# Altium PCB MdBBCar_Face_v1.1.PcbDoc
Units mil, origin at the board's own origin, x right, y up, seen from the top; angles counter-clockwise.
Board outline 2202.88 x 1898.45 mil, 4 copper layers (Top Layer, GND, SIG, Bottom Layer), stack 23.756 mil thick; 72 components, 66 nets, 300 pads, 287 vias.
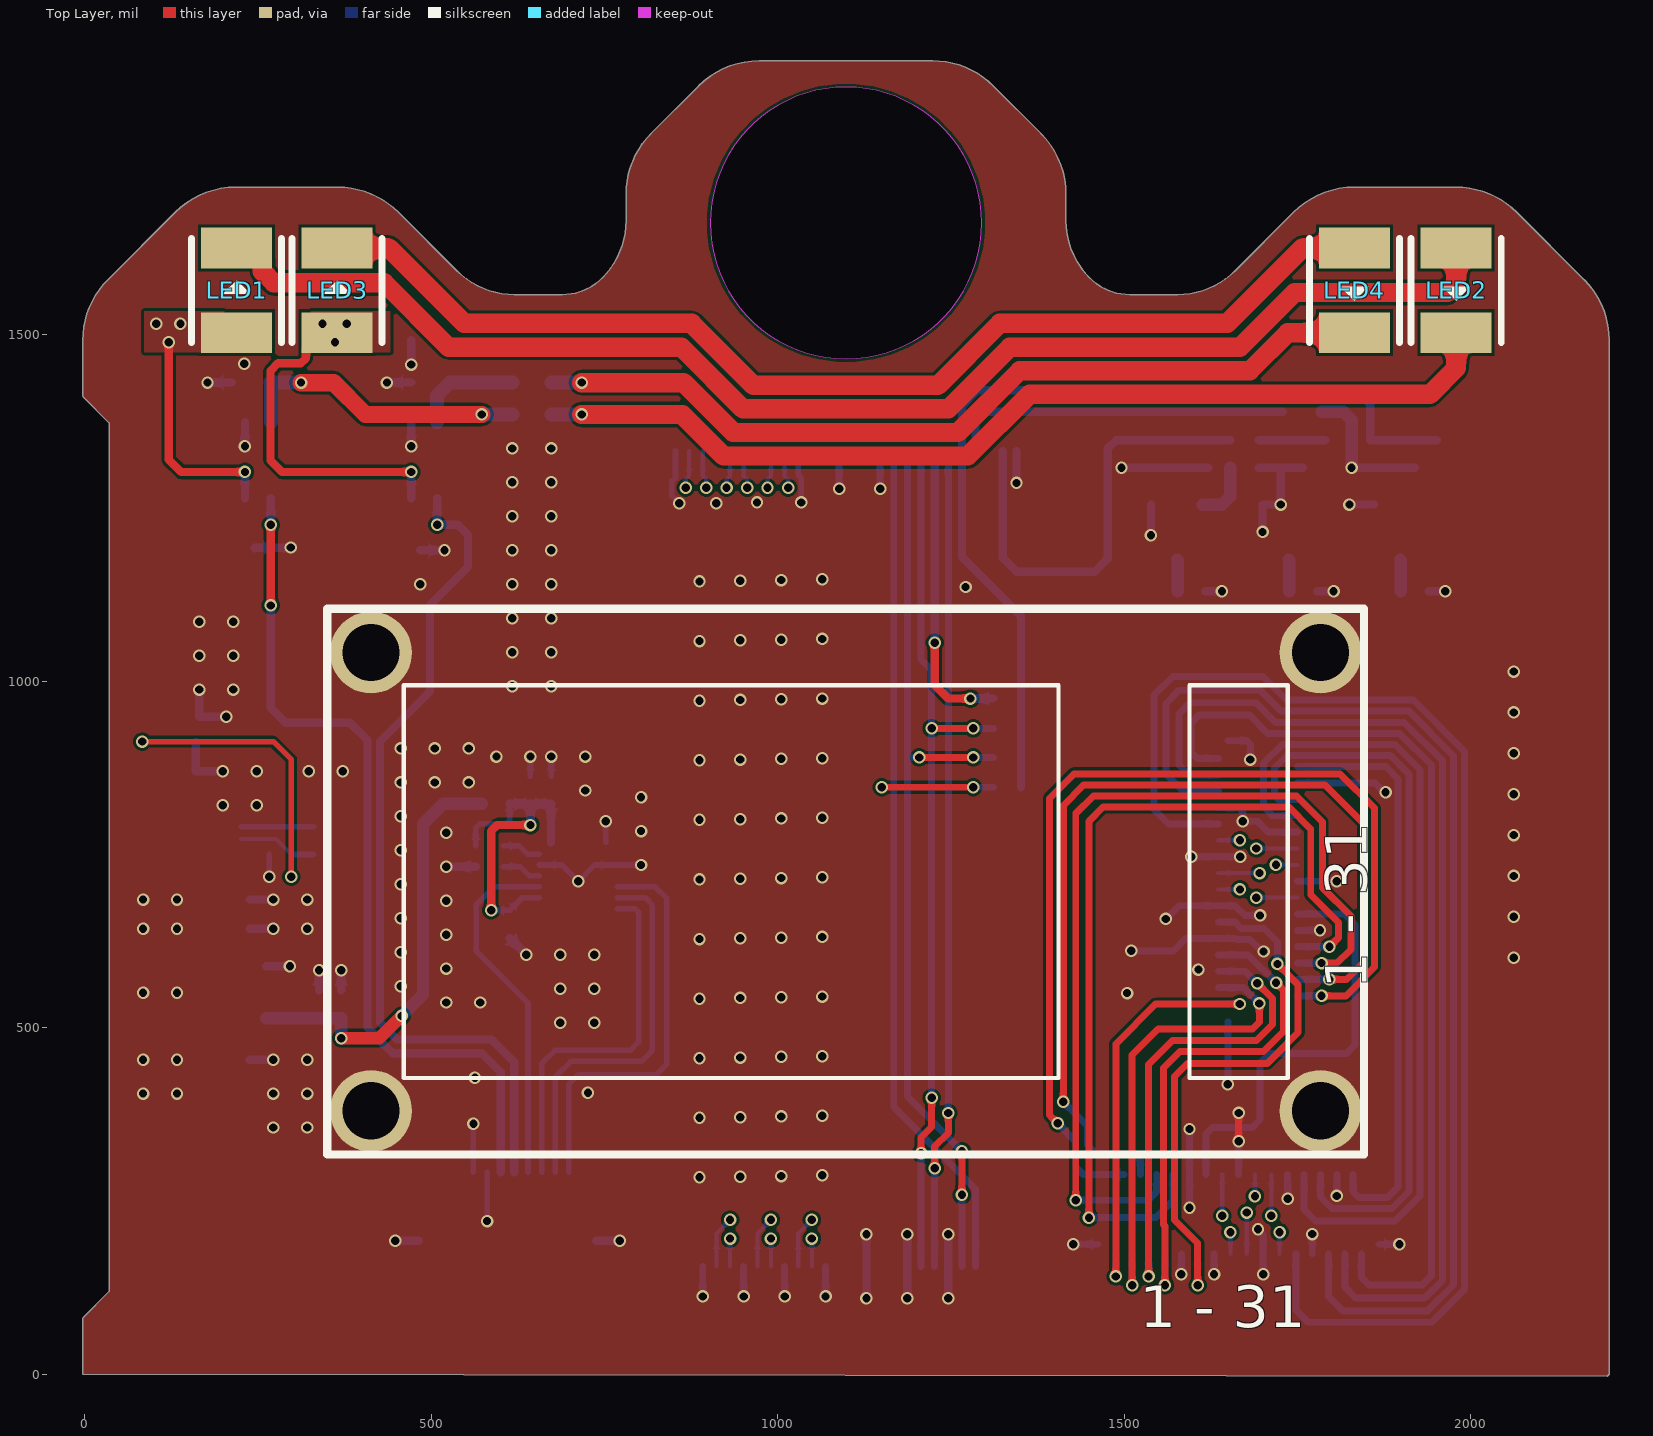
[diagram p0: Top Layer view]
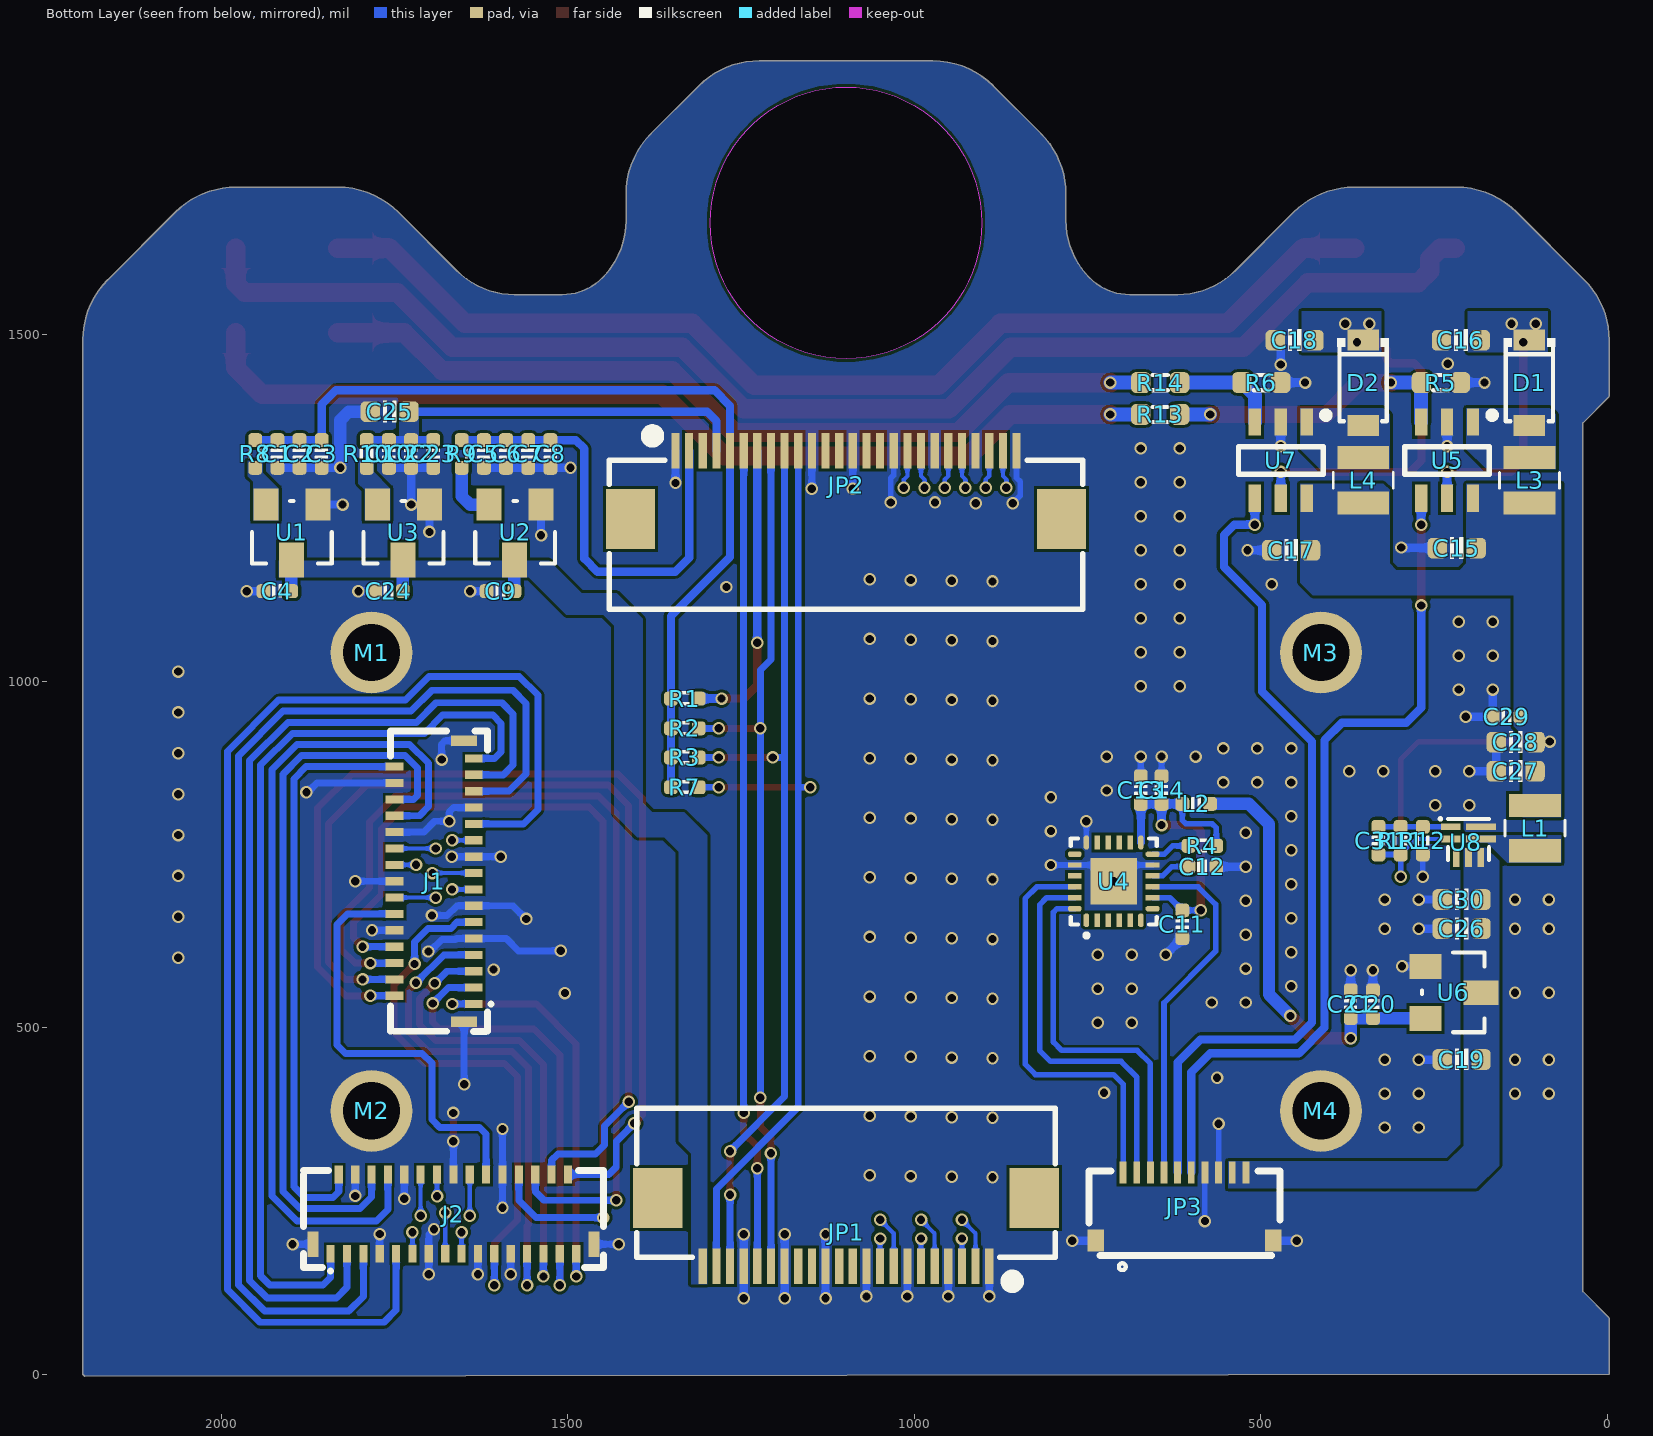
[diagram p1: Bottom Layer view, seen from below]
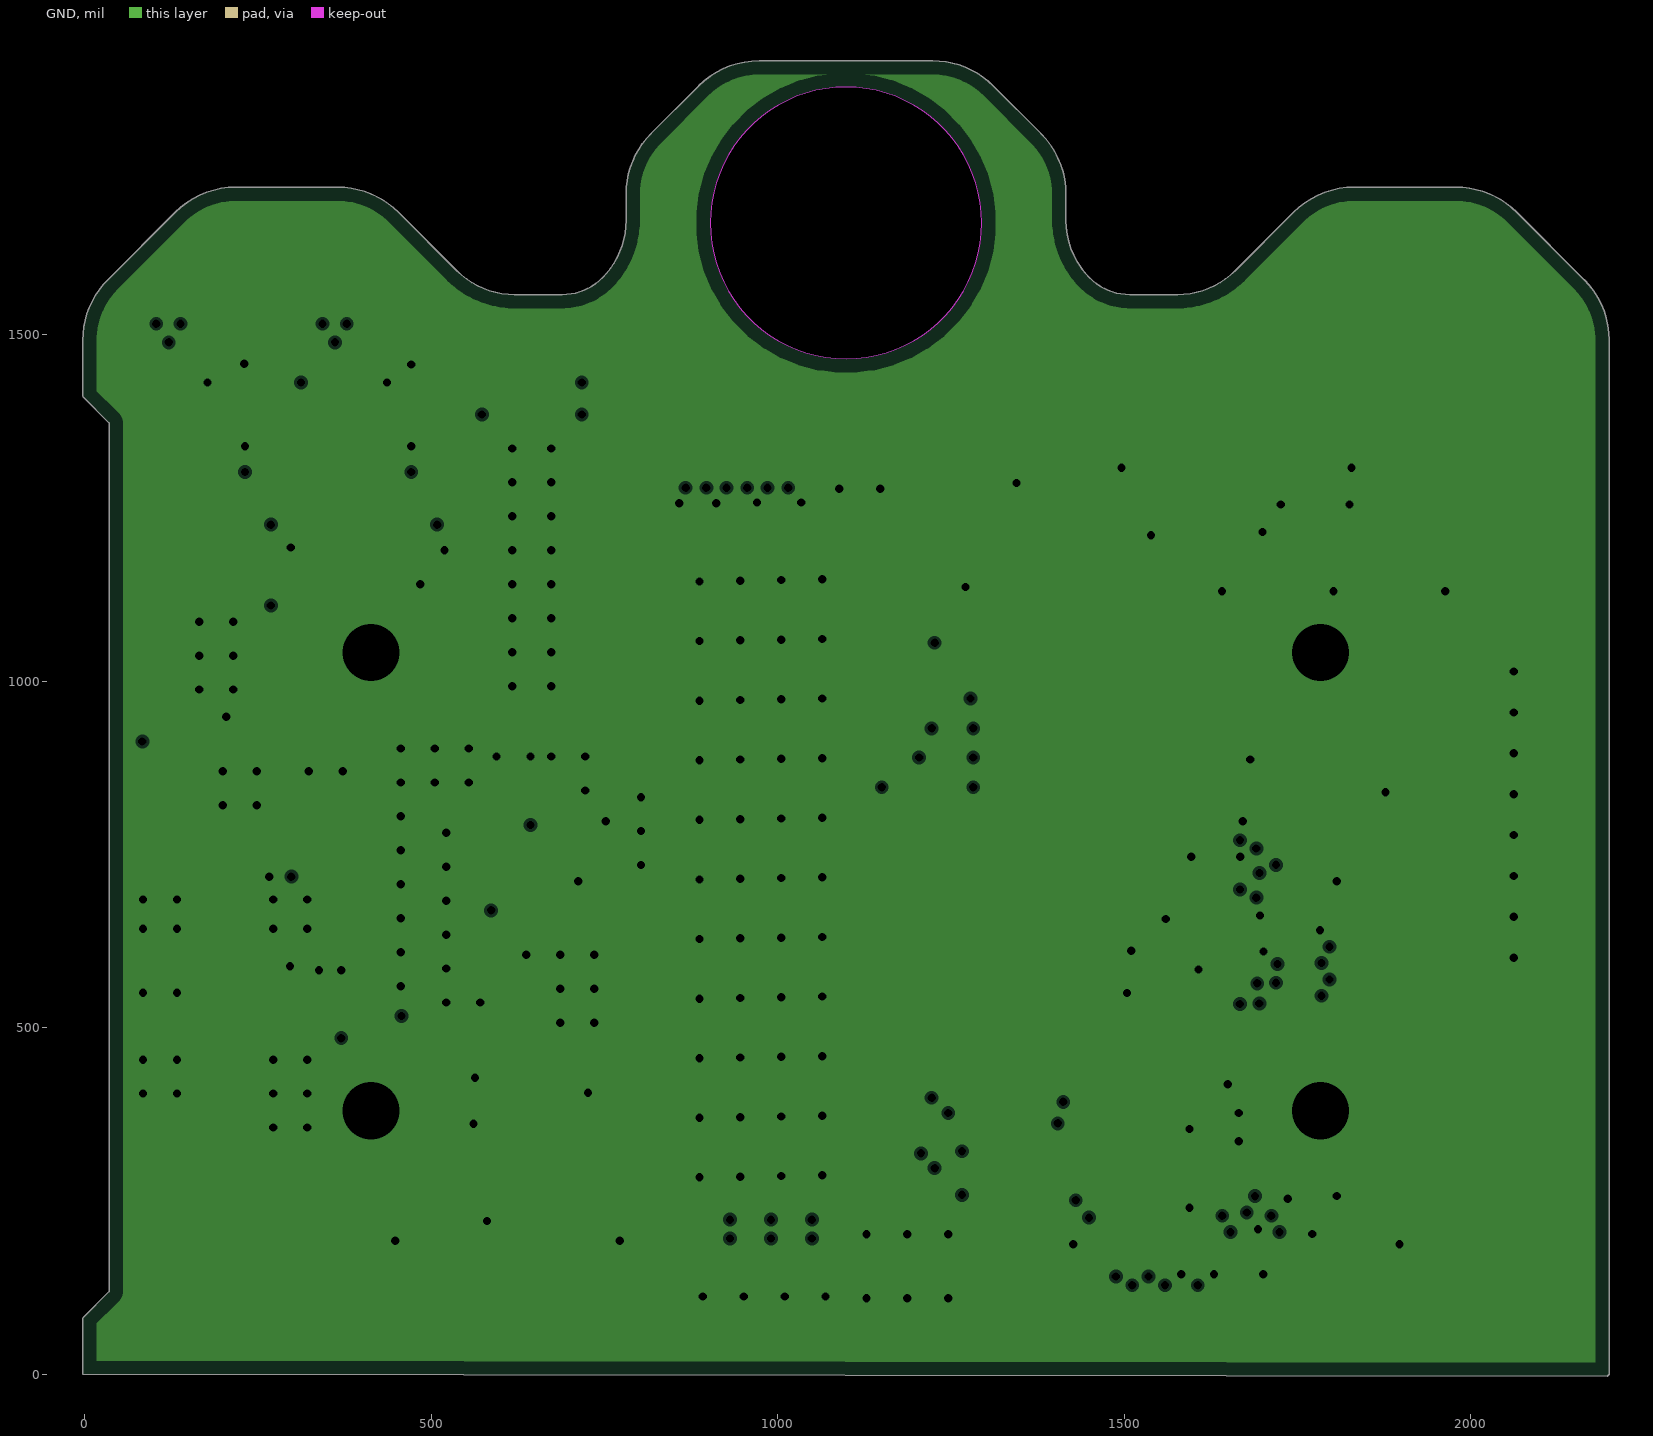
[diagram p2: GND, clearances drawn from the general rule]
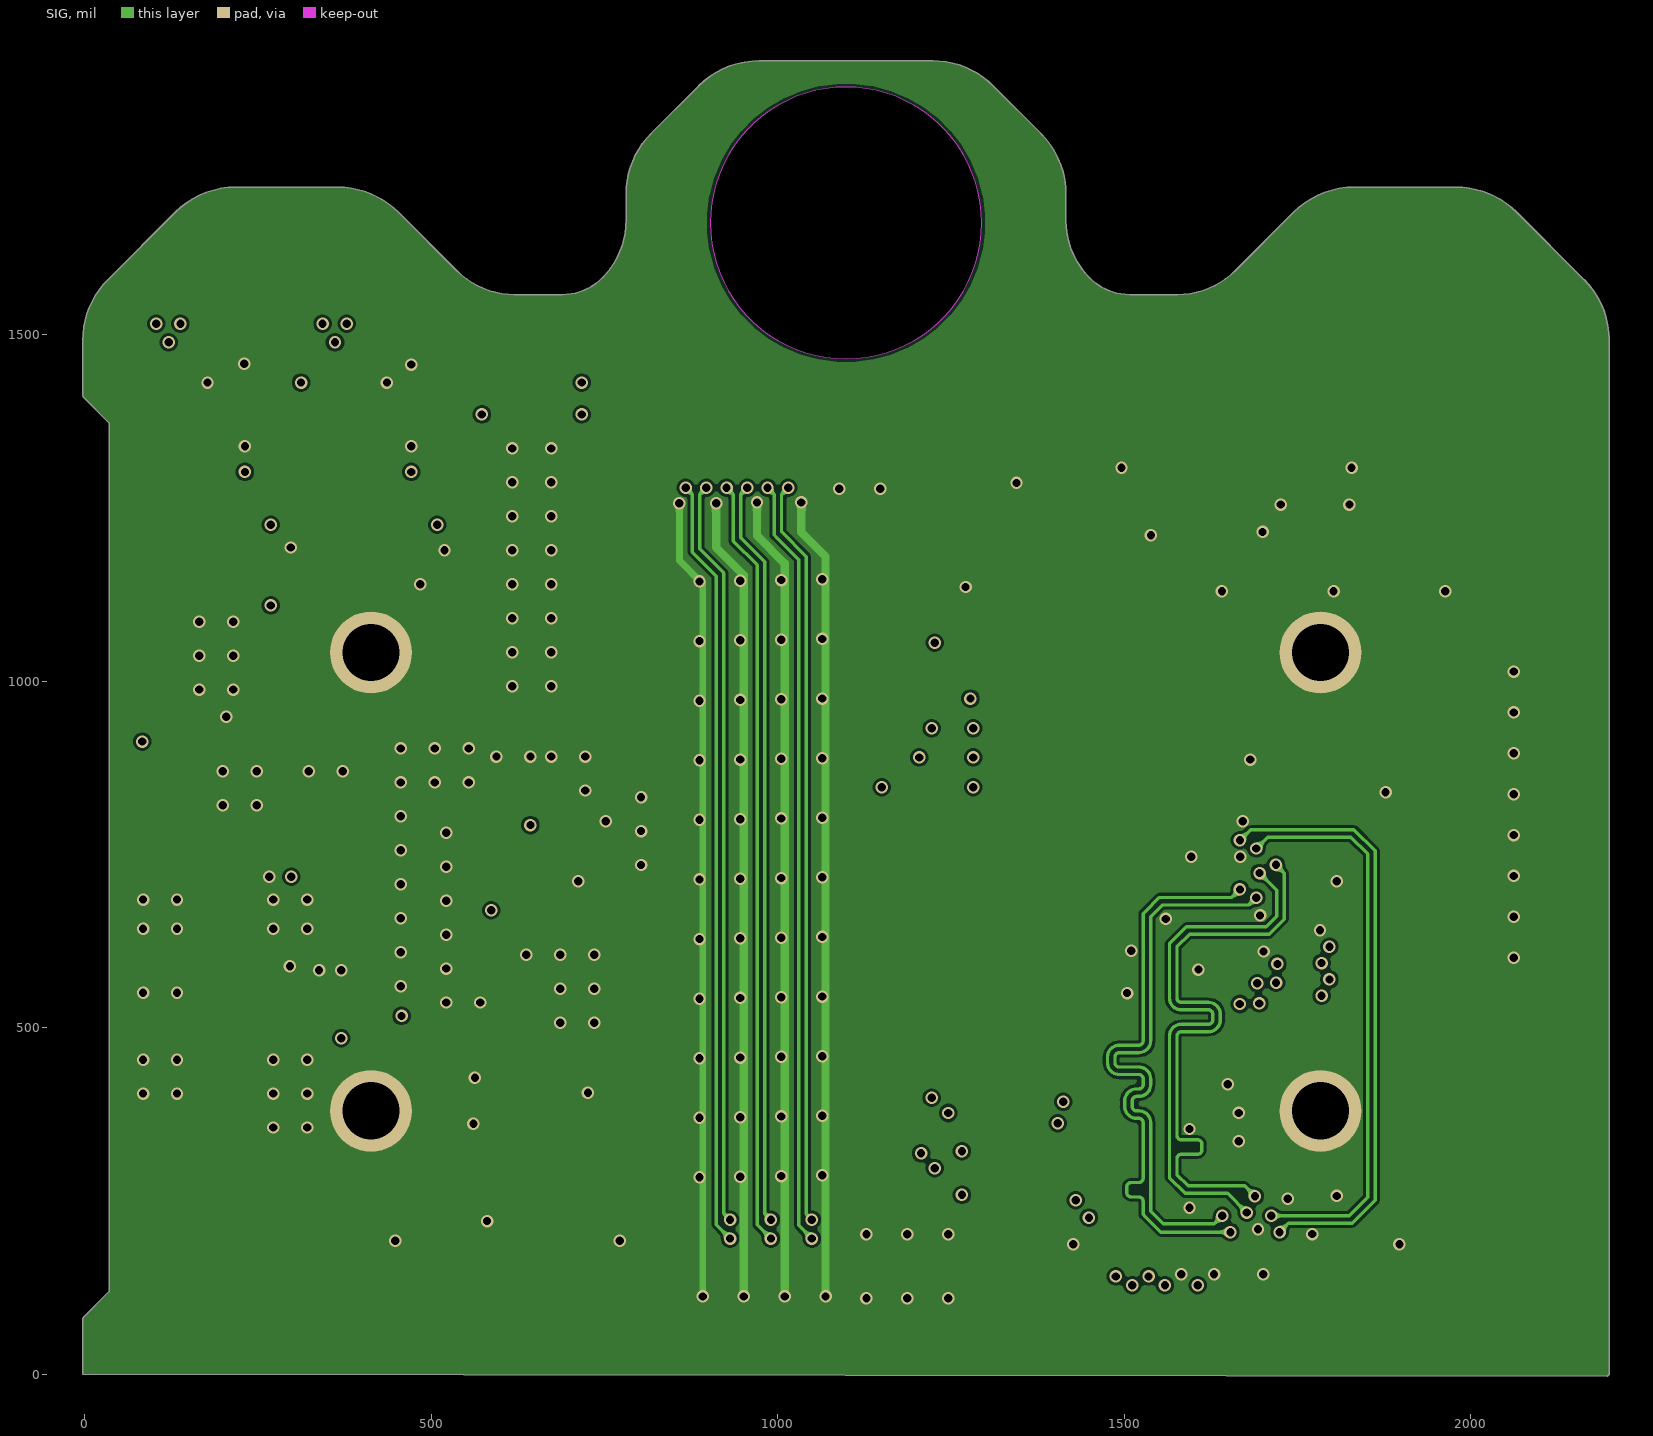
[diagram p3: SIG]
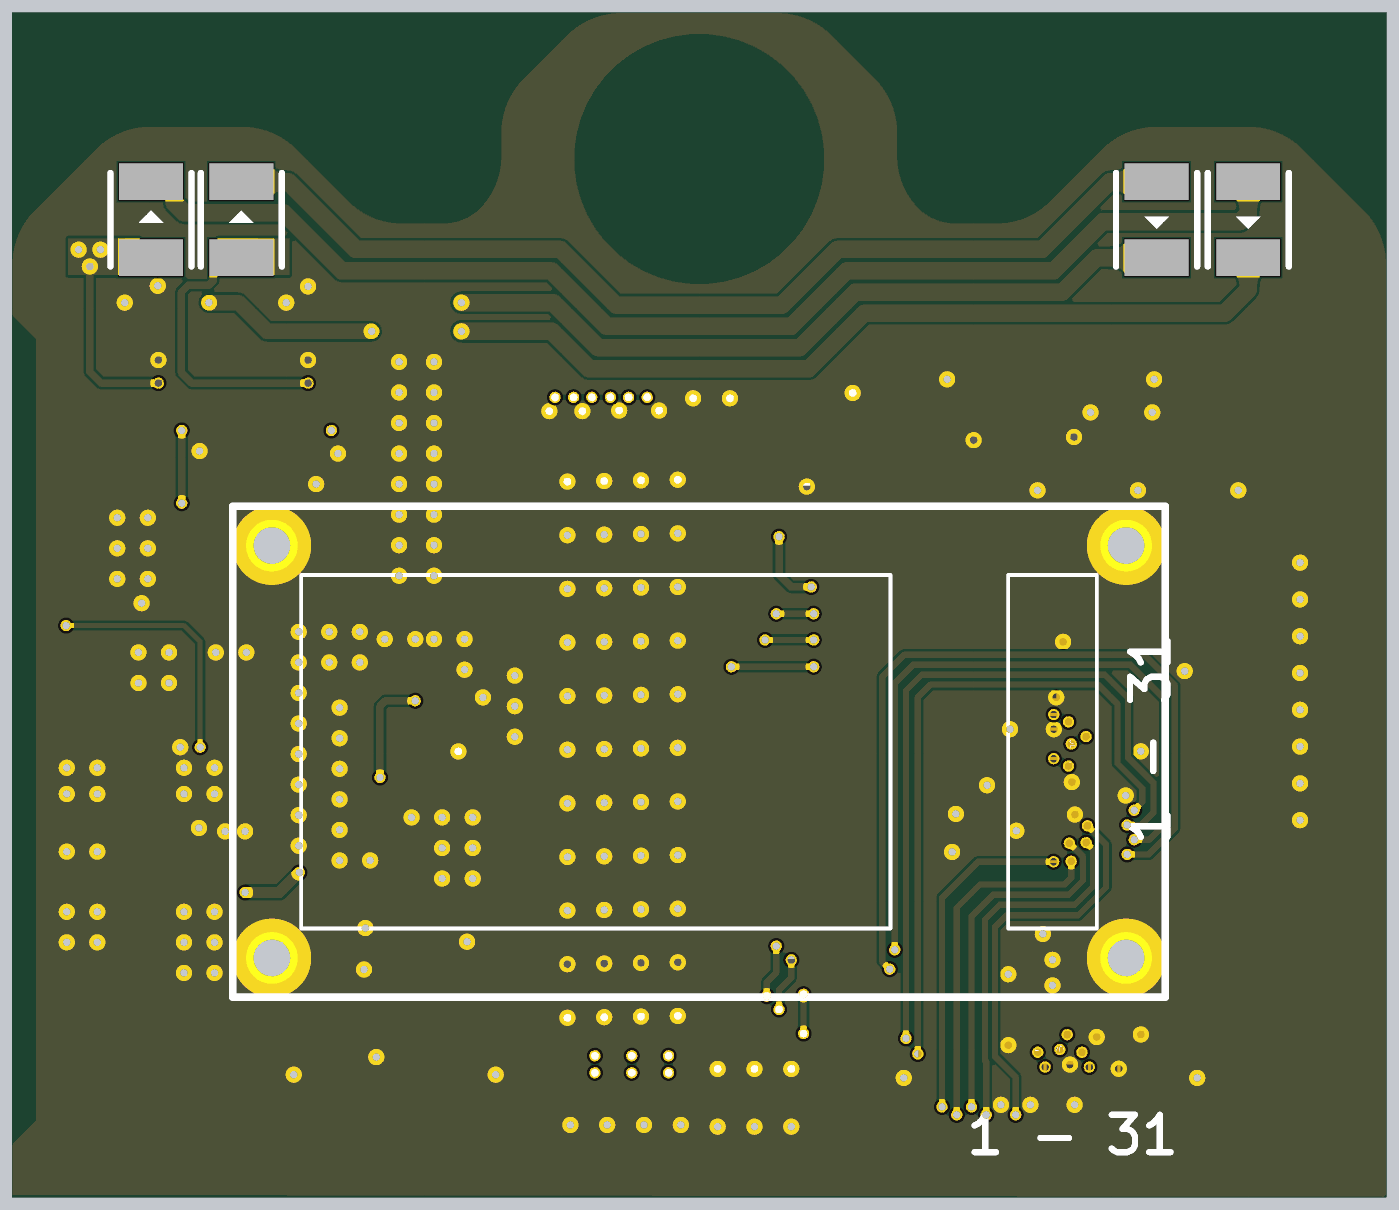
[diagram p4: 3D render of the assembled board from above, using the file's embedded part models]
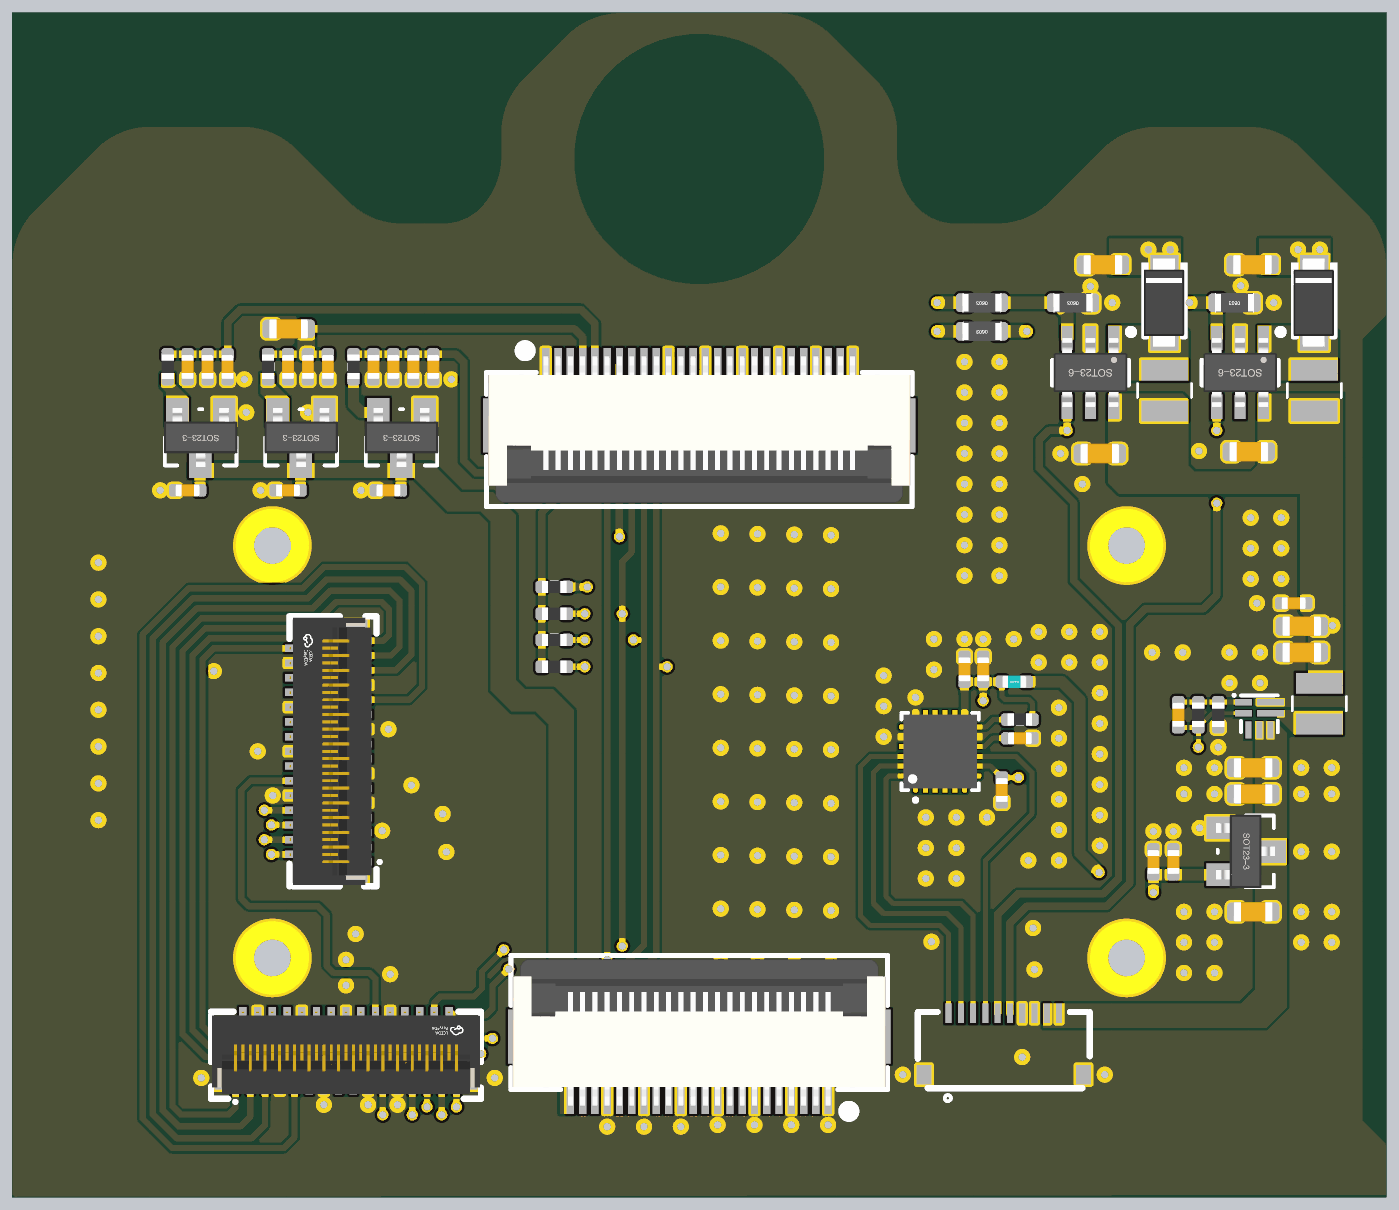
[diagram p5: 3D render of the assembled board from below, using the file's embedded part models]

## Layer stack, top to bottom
Top Solder: solder mask 0.4, Solder Resist, Dk 3.5
Top Layer: signal copper 1.4
Dielectric 2: prepreg 2.8, PP-006, Dk 4.1
GND: plane copper 1.378, net GND
Dielectric 1: dielectric 12.6, FR-4, Dk 4.8
SIG: signal copper 1.378
Dielectric 3: prepreg 2.8, PP-006, Dk 4.1
Bottom Layer: signal copper 1.4
Bottom Solder: solder mask 0.4, Solder Resist, Dk 3.5

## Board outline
-3.02,0 -3.02,80 -2.13,82.13 34.98,119.25 34.98,1372.75 -2.13,1409.87 -3.02,1412 -3.02,1492 cw(c120.71,1492) 33.22,1579.49 130.51,1676.78 cw(c218,1589.29) 218,1713.02 365,1713.02 cw(c365,1589.29) 452.49,1676.78 536.78,1592.49 ccw(c620,1675.71) 620,1558.02 689.15,1558.02 ccw(c689.15,1639.14) 746.51,1581.78 ccw(c663.29,1665) 780.98,1665 780.98,1703 cw(c904.71,1703) 817.22,1790.49 885.94,1859.2 cw(c973.42,1771.71) 973.42,1895.44 1223.42,1895.44 cw(c1223.42,1771.71) 1310.91,1859.2 1379.63,1790.49 cw(c1292.14,1703) 1415.86,1703 1415.86,1665 ccw(c1533.56,1665) 1450.34,1581.78 ccw(c1507.7,1639.14) 1507.7,1558.02 1576.85,1558.02 ccw(c1576.85,1675.71) 1660.07,1592.49 1744.36,1676.78 cw(c1831.85,1589.29) 1831.85,1713.02 1978.85,1713.02 cw(c1978.85,1589.29) 2066.34,1676.78 2163.63,1579.49 cw(c2076.14,1492) 2199.86,1492 2199.86,1422.83 2199.87,0 2196.85,-3.01
cut-out: 902.36,1661.4 ccw(c1098.43,1661.4) 1098.43,1465.34 ccw(c1098.43,1661.4) 1294.49,1661.4 ccw(c1098.43,1661.4) 1098.43,1857.46 ccw(c1098.43,1661.4)

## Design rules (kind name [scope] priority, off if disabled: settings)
Clearance Clearance_1 [OnLayer('Layer 2')] p1: gap=4 ignorepadtopadclearanceinfootprint=FALSE except(6: Arc-Arc Arc-Track Arc-Fill Arc-Poly Arc-Region Track-Track Track-Fill Track-Poly Track-Region Fill-Fill Fill-Poly Fill-Region Poly-Poly Poly-Region Region-Region)
Clearance [All] p2: gap=4 ignorepadtopadclearanceinfootprint=FALSE except(6: Arc-Arc Arc-Track Track-Track)
DiffPairsRouting DiffPairsRouting_1 [InDifferentialPair('MIPI_TX0') Or InDifferentialPair('MIPI_TX1') Or InDifferentialPair('MIPI_TX2') Or InDifferentialPair('CSI_CLK') Or  InDifferentialPair('CSI_D0') Or InDifferentialPair('CSI_D1')] p1: maxlimit=10 minlimit=4 mostfreqgap=6 toplayer_minwidth=4 toplayer_maxwidth=15 toplayer_prefwidth=4.79 midlayer2_minwidth=4.79 midlayer2_maxwidth=15 midlayer2_prefwidth=4.79 bottomlayer_minwidth=4 bottomlayer_maxwidth=15 bottomlayer_prefwidth=4.79 maxuncoupledlength=500
DiffPairsRouting [All] p2: maxlimit=10 minlimit=10 mostfreqgap=10 toplayer_minwidth=15 toplayer_maxwidth=15 toplayer_prefwidth=15 midlayer2_minwidth=15 midlayer2_maxwidth=15 midlayer2_prefwidth=15 bottomlayer_minwidth=15 bottomlayer_maxwidth=15 bottomlayer_prefwidth=15 maxuncoupledlength=500
MatchedLengths MatchedLengths_2 [InNetClass('MIPI_TX2')] p1: tolerance=10 checknetsindiffpair=TRUE checkdiffpairvsdiffpair=FALSE checkxsignals=FALSE checkothers=FALSE
MatchedLengths MatchedLengths_1 [InNetClass('MIPI_TX1')] p2: tolerance=10 checknetsindiffpair=TRUE checkdiffpairvsdiffpair=FALSE checkxsignals=FALSE checkothers=FALSE
MatchedLengths [InNetClass('MIPI_TX0')] p3: tolerance=10 checknetsindiffpair=TRUE checkdiffpairvsdiffpair=FALSE checkxsignals=FALSE checkothers=FALSE
PlaneClearance [All] p1: clearance=4
PlaneConnect [All] p1: planeconnectstyle=Direct reliefexpansion=20 reliefentries=4 reliefconductorwidth=10 reliefairgap=10
PolygonConnect [All] p1: connectstyle=Direct reliefconductorwidth=10 reliefentries=4 polygonreliefangle="90 Angle" airgapwidth=10
RoutingVias [All] p1: holewidth=12 width=50 viastyle="Through Hole" minholewidth=12 minwidth=18 maxholewidth=28 maxwidth=18
SolderMaskExpansion [All] p1: expansion=4 istentingtop=FALSE
Width [All] p1: maxlimit=60 minlimit=3.5 preferedwidth=10
27 further rules are at their usual default settings.

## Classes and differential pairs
net class CSI_: CSI_CLK_N CSI_CLK_P CSI_D0_N CSI_D0_P CSI_D1_N CSI_D1_P
net class MIPI_TX2: MIPI_TX2_N MIPI_TX2_P
net class MIPI_TX1: MIPI_TX1_N MIPI_TX1_P
net class MIPI_TX0: MIPI_TX0_N MIPI_TX0_P
differential pair CSI_D1: +CSI_D1_P -CSI_D1_N
differential pair CSI_D0: +CSI_D0_P -CSI_D0_N
differential pair CSI_CLK: +CSI_CLK_P -CSI_CLK_N
differential pair MIPI_TX2: +MIPI_TX2_P -MIPI_TX2_N
differential pair MIPI_TX1: +MIPI_TX1_P -MIPI_TX1_N
differential pair MIPI_TX0: +MIPI_TX0_P -MIPI_TX0_N

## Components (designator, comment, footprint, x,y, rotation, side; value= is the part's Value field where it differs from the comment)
C1 "10uF" "C 0402_L" 1919,1328 r270 bottom
C2 "100nF" "C 0402_L" 1887,1328 r270 bottom
C3 "100nF" "C 0402_L" 1855,1328 r270 bottom
C4 "10uF" "C 0402_L" 1919,1130 r0 bottom
C5 "10uF" "C 0402_L" 1621,1328 r270 bottom
C6 "100nF" "C 0402_L" 1589,1328 r270 bottom
C7 "100nF" "C 0402_L" 1557,1328 r270 bottom
C8 "100nF" "C 0402_L" 1525,1328 r270 bottom
C9 "10uF" "C 0402_L" 1597,1130 r0 bottom
C10 "10uF" "C 0402_L" 1758,1328 r270 bottom
C11 "100nF" "C 0402_L" 613.06,649.4 r90 bottom
C12 "100nF" "C 0402_L" 584.06,732.4 r0 bottom
C13 "100nF" "C 0402_L" 673,843 r90 bottom
C14 "2.2uF" "C 0402_L" 643,843 r90 bottom
C15 "10uF" "C 0603_L" 217,1192 r180 bottom
C16 "10uF" "C 0603_L" 211,1492 r180 bottom
C17 "10uF" "C 0603_L" 456,1189 r180 bottom
C18 "10uF" "C 0603_L" 451,1492 r180 bottom
C19 "10uF" "C 0603_L" 210,454 r180 bottom
C20 "1uF" "C 0402_L" 338,534 r90 bottom
C21 "0.1uF" "C 0402_L" 370,534 r90 bottom
C22 "100nF" "C 0402_L" 1726,1328 r270 bottom
C23 "100nF" "C 0402_L" 1694,1328 r270 bottom
C24 "10uF" "C 0402_L" 1758,1130 r0 bottom
C25 "47uF" "C 0603_L" 1757,1389 r180 bottom
C26 "22uF" "C 0603_L" 210,643 r180 bottom
C27 "22uF" "C 0603_L" 132,870 r180 bottom
C28 "22uF" "C 0603_L" 132,912 r180 bottom
C29 "100nF" "C 0402_L" 145,949 r0 bottom
C30 "22uF" "C 0603_L" 210,685 r180 bottom
C31 "6.8pF" "C 0402_L" 330,770 r270 bottom
D1 "DSS34" SOD-123FL 115,1431 r270 bottom
D2 "DSS34" SOD-123FL 355,1431 r270 bottom
J1 "FPC-31P(交错脚)" "FPC 1H-WS-31P" 1692.91,711.42 r90 bottom
J2 "FPC-31P(交错脚)" "FPC 1H-WS-31P" 1665,231 r180 bottom
JP1 "FPC1.0-22P" "FPC0.5 2H-WS-22P" 1098.43,254 r0 bottom
JP2 "FPC1.0-26P" "FPC0.5 2H-WS-26P" 1098.43,1234 r180 bottom
JP3 "FPC1.0-10P" "FPC0.5 1H-WS-10P" 610,242 r180 bottom
L1 "FTC252012S2R2" 252012 104,788 r90 bottom
L2 "BLM15AX102SN1D" "L 0402" 593,823 r0 bottom
L3 "FTC252010S4R7MBCA" 252012 112,1290 r90 bottom
L4 "FTC252010S4R7MBCA" 252012 352,1290 r90 bottom
LED1 "红外" "LED 3528-2Pin" 219,1564 r270 top
LED2 "红外" "LED 3528-2Pin" 1979,1564 r90 top
LED3 "白色" "LED 3528-2Pin" 364,1564 r270 top
LED4 "白色" "LED 3528-2Pin" 1832,1564 r90 top
M1 "NUT" SMT-NUT-M1610 1783.07,1041.41 r180 bottom
M2 "NUT" SMT-NUT-M1610 1783.07,379.99 r180 bottom
M3 "NUT" SMT-NUT-M1610 412.99,1041.41 r180 bottom
M4 "NUT" SMT-NUT-M1610 412.99,379.99 r180 bottom
R1 "100K" "R 0402_L" 1331,975 r0 bottom
R2 "100K" "R 0402_L" 1331,932 r0 bottom
R3 "5.1K" "R 0402_L" 1331,890 r0 bottom
R4 "10K" "R 0402_L" 584.06,762.4 r180 bottom
R5 "2R" "R 0603_L" 240,1431 r0 bottom
R6 "1R" "R 0603_L" 499,1431 r0 bottom
R7 "5.1K" "R 0402_L" 1331,847 r0 bottom
R8 "0R" "R 0402_L" 1951,1328 r270 bottom
R9 "0R" "R 0402_L" 1653,1328 r270 bottom
R10 "0R" "R 0402_L" 1790,1328 r270 bottom
R11 "450K" "R 0402_L" 298,770 r270 bottom
R12 "120K" "R 0402_L" 266,770 r90 bottom
R13 "0R" "R 0603_L" 645,1385 r0 bottom
R14 "0R" "R 0603_L" 645,1431 r0 bottom
U1 "CJ6206A18N" SOT23-3L 1898,1215 r0 bottom
U2 "CJ6206A12M" SOT23-3L 1576,1215 r0 bottom
U3 "CJ6206A28N" SOT23-3L 1737,1215 r0 bottom
U4 "MPU6500" "QFN24 3X3" 712.13,711.2 r180 bottom
U5 "AP3031KTR-G1" SOT23-6L 231,1319 r0 bottom
U6 "CJ6206A33M" SOT23-3L 222,551 r270 bottom
U7 "AP3031KTR-G1" SOT23-6L 471,1319 r0 bottom
U8 "SY8843QWC" "QFN7 1.5X1.5" 204,768 r180 bottom

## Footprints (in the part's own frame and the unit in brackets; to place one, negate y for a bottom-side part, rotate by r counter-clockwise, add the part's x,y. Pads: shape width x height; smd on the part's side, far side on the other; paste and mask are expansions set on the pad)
252012 [mm]
  rect 0.85x1.905 smd: 1(-0.83,0) 2(0.83,0)
  silkscreen extent -0.29,-1.1 0.29,1.1, body extent -1.25,-1 1.25,1, height 1.2
"C 0402_L" [mil] "无极性贴片电容"
  rrect50% 20x20 smd: 1(20,0) 2(-20,0)
  silkscreen extent -7,-9 7,9, body extent -20,-10 20,10, height 20
"C 0603_L" [mil] "无极性贴片电容"
  rrect50% 28x30 smd: 1(-28,0) 2(28,0)
  silkscreen extent -10,-15 10,15, body extent -31,-16 31,16, height 31
"FPC0.5 1H-WS-10P" [mm]
  rect 0.6x0.8 smd: 0(-3.25,-1.25) 0(3.25,-1.25)
  rect 0.25x0.8 smd: 1(-2.25,1.25) 2(-1.75,1.25) 3(-1.25,1.25) 4(-0.75,1.25) 5(-0.25,1.25) 6(0.25,1.25) 7(0.75,1.25) 8(1.25,1.25) 9(1.75,1.25) 10(2.25,1.25)
  silkscreen extent -3.5,-2.33 3.5,1.3
"FPC0.5 2H-WS-22P" [mm] "长：15.2mm，宽：5.2mm，高：2mm"
  rect 1.8x2.2 smd: 0(-6.9,0) 0(6.9,0)
  rect 0.3x1.3 smd: 1(-5.25,2.497) 2(-4.75,2.497) 3(-4.25,2.497) 4(-3.75,2.497) 5(-3.25,2.497) 6(-2.75,2.497) 7(-2.25,2.497) 8(-1.75,2.497) 9(-1.25,2.497) 10(-0.75,2.497) 11(-0.25,2.497) 12(0.25,2.497) 13(0.75,2.497) 14(1.25,2.497) 15(1.75,2.497) 16(2.25,2.497) 17(2.75,2.497) 18(3.25,2.497) 19(3.75,2.497) 20(4.25,2.497) 21(4.75,2.497) 22(5.25,2.497)
  silkscreen extent -7.68,-3.3 7.68,3.23, body extent -7.6,-3.15 7.6,2.85, height 2
"FPC0.5 2H-WS-26P" [mm] "长：17.2mm，宽：5.2mm，高：2mm"
  rect 1.8x2.2 smd: 0(-7.9,0) 0(7.9,0)
  rect 0.3x1.3 smd: 1(-6.25,2.497) 2(-5.75,2.497) 3(-5.25,2.497) 4(-4.75,2.497) 5(-4.25,2.497) 6(-3.75,2.497) 7(-3.25,2.497) 8(-2.75,2.497) 9(-2.25,2.497) 10(-1.75,2.497) 11(-1.25,2.497) 12(-0.75,2.497) 13(-0.25,2.497) 14(0.25,2.497) 15(0.75,2.497) 16(1.25,2.497) 17(1.75,2.497) 18(2.25,2.497) 19(2.75,2.497) 20(3.25,2.497) 21(3.75,2.497) 22(4.25,2.497) 23(4.75,2.497) 24(5.25,2.497) 25(5.75,2.497) 26(6.25,2.497)
  silkscreen extent -8.68,-3.3 8.68,3.23, body extent -8.6,-3.15 8.6,2.85, height 2
"FPC 1H-WS-31P" [mm]
  rect 0.3x0.65 smd: 1(-4.5,-1.453) 2(-4.2,1.453) 3(-3.9,-1.453) 4(-3.6,1.453) 5(-3.3,-1.453) 6(-3,1.453) 7(-2.7,-1.453) 8(-2.4,1.453) 9(-2.1,-1.453) 10(-1.8,1.453) 11(-1.5,-1.453) 12(-1.2,1.453) 13(-0.9,-1.453) 14(-0.6,1.453) 15(-0.3,-1.453) 16(0,1.453) 17(0.3,-1.453) 18(0.6,1.453) 19(0.9,-1.453) 20(1.2,1.453) 21(1.5,-1.453) 22(1.8,1.453) 23(2.1,-1.453) 24(2.4,1.453) 25(2.7,-1.453) 26(3,1.453) 27(3.3,-1.453) 28(3.6,1.453) 29(3.9,-1.453) 30(4.2,1.453) 31(4.5,-1.453)
  rect 0.4x0.95 smd: 32(-5.15,-1.103) 33(5.15,-1.103)
  silkscreen extent -5.5,-2.08 5.5,1.6, body extent -5.45,-1.75 5.45,1.65, height 1
"L 0402" [mil] "小功率贴片电感"
  rrect50% 20x20 smd: 1(20,0) 2(-20,0)
  silkscreen extent -6,-9 6,9, body extent -20,-10 20,10, height 20
"LED 3528-2Pin" [mm] "2脚，3528LED"
  rect 1.5x2.6 smd paste+0 mask+0.05: 1(-1.55,0) 2(1.55,0)
  silkscreen extent -1.9,-1.65 1.91,1.65, body extent -1.77,-1.4 1.73,1.4, height 1.95
"QFN7 1.5X1.5" [mm]
  rect 0.7x0.25 smd paste+0 mask+0.05: 1(-0.55,0.563) 2(-0.55,0.113)
  rect 0.25x0.7 smd paste+0 mask+0.05: 3(-0.35,-0.563) 4(0.1,-0.563) 5(0.55,-0.563)
  rect 1.1x0.25 smd paste+0 mask+0.05: 6(0.55,0.113) 7(0.55,0.563)
  silkscreen extent -0.98,-0.66 0.85,0.9
"QFN24 3X3" [mm]
  oct 0.2x0.505 smd paste-100 mask+0.051: 1(-1,-1.427) 6(1,-1.427) 13(1,1.427) 18(-1,1.427)
  rect 0.2x0.505 smd paste-100 mask+0.051: 2(-0.6,-1.427) 3(-0.2,-1.427) 4(0.2,-1.427) 5(0.6,-1.427) 14(0.6,1.427) 15(0.2,1.427) 16(-0.2,1.427) 17(-0.6,1.427)
  oct 0.505x0.2 smd paste-100 mask+0.051: 7(1.427,-1) 12(1.427,1) 19(-1.427,1) 24(-1.427,-1)
  rect 0.505x0.2 smd paste-100 mask+0.051: 8(1.427,-0.6) 9(1.427,-0.2) 10(1.427,0.2) 11(1.427,0.6) 20(-1.427,0.6) 21(-1.427,0.2) 22(-1.427,-0.2) 23(-1.427,-0.6)
  rect 1.7x1.7 smd paste-100 mask+0.051: 25(0,0)
  silkscreen extent -1.58,-2.05 1.58,1.58, body extent -1.5,-1.5 1.5,1.5, height 0.98
"R 0402_L" [mil] "1/16W贴片电阻"
  rrect50% 20x20 smd: 1(20,0) 2(-20,0)
  silkscreen extent -6,-9 6,10, body extent -20,-10 20,10, height 14
"R 0603_L" [mil] "1/10W贴片电阻"
  rrect50% 28x30 smd: 1(-28,0) 2(28,0)
  silkscreen extent -11,-11 11,11, body extent -31,-16 31,16, height 16
SMT-NUT-M1610 [mm]
  round 3 hole 2.1: 1(0,0)
  body extent -1.5,-1.5 1.5,1.5, height 1
SOD-123FL [mil]
  rect 30x45.28 smd: 1(-61.3,2.79) 2(61.96,2.79)
  silkscreen extent -64,-34 56,40, body extent -71,-30 71,34, height 37
SOT23-3L [mil] "3x1.3x1mm(长宽高)"
  rect 36x46 smd: 1(-37.5,-40) 2(37.5,-40)
  rect 36x50 smd: 3(0.5,40)
  silkscreen extent -57,-45 58,45, body extent -59,-47 59,47, height 41
SOT23-6L [mm] "3x1.6x1.1mm(长宽高)"
  rect 0.45x1 smd: 1(-0.95,-1.397) 2(0,-1.397) 3(0.95,-1.397) 4(0.95,1.397) 5(0,1.397) 6(-0.95,1.397)
  silkscreen extent -1.77,-1.78 1.55,0.51, body extent -1.5,-1.4 1.5,1.4, height 1.15

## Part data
C1 C2 C3 C4 C5 C6 C7 C8 C9 C10 C11 C12 C13 C14 C15 C16 C17 C18 C19 C20 C21 C22 C23 C24 C25 C26 C27 C28 C29 C30 C31: library part C, "无极性贴片电容"
D1 D2: "肖特基二极管"
J1 J2: "FPC连接器"
JP1: library part FPC-22P, "FPC连接器"
JP2: library part FPC-26P, "FPC连接器"
JP3: library part FPC-10P, "FPC连接器"
L1 L3 L4: library part L-CD, "贴片功率电感"
L2: library part L, "小功率贴片电感"
LED1 LED2 LED3 LED4: library part LED-SMD, "贴片LED"
M1 M2 M3 M4: library part SMTNUT, "SMT表贴螺母"
R1 R2 R3 R4 R5 R6 R7 R8 R9 R10 R11 R12 R13 R14: library part R, "贴片电阻"
U1 U2 U3 U6: library part LN6206PXXX, "三端稳压芯片 / 6V 250mA"
U4: "6轴IMU"
U5 U7: library part AP3031, "LED驱动"
U8: "DC-DC 1.5M / VIN:2.7~5.5V 3A"

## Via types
v1: diameter 18, hole 12, Top Layer to Bottom Layer, 287 vias

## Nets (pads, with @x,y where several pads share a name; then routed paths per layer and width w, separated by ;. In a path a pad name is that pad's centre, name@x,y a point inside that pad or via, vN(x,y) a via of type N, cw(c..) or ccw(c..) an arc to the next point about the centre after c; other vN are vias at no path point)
5V: C19.2 C26.2 C30.2 JP3.9 JP3.10 U6.3 U8.4 U8.5
AVCC_3V3: C20.2 C21.2 L2.2 U6.2 | length 624.3
  Top Layer w18: v1(370,485) 425,485 v1(457,517)
  Bottom Layer w18: U6.2 369.5,513.5 C21.2 v1(370,485) ; v1(457,517) 488,548 488,794 517,823 L2.2
AVDD_2V8: C10.2 C22.2 C23.2 C25.2 JP2.4 R10.2 | length 588.2
  Bottom Layer w12: JP2.4 1285.43,1375.3 1299.13,1389 C25.2 ; C23.2 C22.2 C10.2 R10.2
C1: J1.1 J2.31 | length 602.5
  Top Layer w10: v1(1487.84,141.07) 1487.84,476.84 1545.25,534.25 v1(1666.87,534.25)
  Bottom Layer w10: v1(1487.84,141.07) J2.31 ; J1.1 v1(1666.87,534.25)
C2: J1.2 J2.30 | length 1483.6
  Top Layer w10: v1(1404,362) 1392,374 1392,831 1427.4,866.4 1811.6,866.4 1861,817 1861,587.37 1819.69,546.06 v1(1784.69,546.06)
  Bottom Layer w10: v1(1404,362) 1430,336 1430,299 1440.8,288.2 J2.30 ; J1.2 v1(1784.69,546.06)
C3: J1.3 J2.29 | length 676.7
  Top Layer w10: v1(1511.45,128.3) 1511.45,460.45 1549,498 1685,498 1695,508 v1(1695,535)
  Bottom Layer w10: v1(1511.45,128.3) J2.29 ; J1.3 1672.13,557.87 v1(1695,535)
C4: J1.4 J2.28 | length 1384.6
  Top Layer w10: v1(1412,393) 1412,821 1441.4,850.4 1789.6,850.4 1845,795 1845,594 1820.68,569.68 v1(1796.07,569.68)
  Bottom Layer w10: v1(1412,393) 1447,358 1447,331 1460,318 1514,318 1523.27,308.74 J2.28 ; J1.4 v1(1796.07,569.68)
C5: J1.5 J2.27 | length 673.7
  Top Layer w10: v1(1535.07,141.07) 1535.07,447.07 1569.4,481.4 1691.03,481.4 1714,504.37 1714,542 v1(1692,564)
  Bottom Layer w10: v1(1535.07,141.07) J2.27 ; J1.5 1674.51,581.49 v1(1692,564)
C6: J1.6 J2.26 | length 1372.6
  Top Layer w10: v1(1430,251) 1430,809 1455.4,834.4 1748.6,834.4 1786,797 1786,702 1827,661 1827,613 1807.31,593.31 v1(1784.69,593.31)
  Bottom Layer w10: v1(1430,251) 1534,251 1546.89,263.89 J2.26 ; J1.6 v1(1784.69,593.31)
C7: J1.7 J2.25 | length 729.8
  Top Layer w10: v1(1558.7,128.3) 1558.7,213.67 1556.7,215.67 1556.7,441.7 1580.4,465.4 1700.73,465.4 1730,494.67 1730,554 v1(1719,565)
  Bottom Layer w10: v1(1558.7,128.3) J2.25 ; J1.7 1678.88,605.12 v1(1719,565)
C8: J1.8 J2.24 | length 1320.8
  Top Layer w10: v1(1449,226) 1449,798 1469.4,818.4 1737.6,818.4 1769.06,786.94 1769.06,691.94 1809,652 1809,629.86 v1(1796.07,616.93)
  Bottom Layer w10: v1(1449,226) 1546,226 1570.52,250.51 J2.24 ; J1.8 v1(1796.07,616.93)
C11: J1.11 J2.21 | length 805.6
  Top Layer w10: v1(1605.94,128.3) 1605.94,189.05 1572.7,222.3 1572.7,429.7 1591.4,448.4 1706.36,448.4 1751,493.04 1751,562 v1(1721,592)
  Bottom Layer w10: v1(1605.94,128.3) J2.21 ; J1.11 1659.64,652.36 1668.76,643.24 1701.76,643.24 1721,624 v1(1721,592)
C12: J1.12 J2.20 | length 637.9
  Bottom Layer w10: J2.20 1617.76,346.63 1627.13,356 1684.72,356 1696,367.28 1696,449 1710,463 1821,463 1833,475 1833,649 1817.83,664.17 J1.12
C23: J1.23 J2.9 | length 1898.7
  Bottom Layer w10: J1.23 1563.88,794.09 1543.06,814.91 1543.06,980.06 1570,1007 1700,1007 1734.23,972.77 1917.23,972.77 1991.06,898.94 1991.06,122.18 1943.88,75 1765,75 1747.68,92.32 J2.9
C24: J1.24 J2.8 | length 1224.9
  Bottom Layer w10: J1.24 1714.1,805.9 1701,819 1701,881.71 1728.06,908.77 1890.72,908.77 1927.06,872.43 1927.06,257.26 1890.8,221 1776,221 1759.48,237.51 J2.8
C26: J1.26 J2.6 | length 1067.6
  Bottom Layer w10: J1.26 1722.86,829.53 1717,835.39 1717,875.08 1734.69,892.77 1884.09,892.77 1911.06,865.8 1911.06,263.89 1886.18,239 1799.54,239 1783.1,255.44 J2.6
C27: J1.27 J2.5 | length 1679.8
  Bottom Layer w10: J1.27 1584.66,841.34 1560,866 1560,968 1579,987 1696,987 1726.23,956.77 1910.6,956.77 1975.06,892.31 1975.06,128.81 1937.25,91 1816,91 1794.93,112.07 J2.5
C29: J1.29 J2.3 | length 1513.8
  Bottom Layer w10: J1.29 1593.04,864.96 1579,879 1579,953 1595,969 1690,969 1718.23,940.77 1903.97,940.77 1959.06,885.68 1959.06,135.44 1933.63,110 1834,110 1818.55,125.45 J2.3
C30: J1.30 J2.2 | length 840.2
  Bottom Layer w10: J1.30 1877.46,876.77 1895.06,859.17 1895.06,270.51 1879.55,255 1839,255 1830.35,263.64 J2.2
C31: J1.31 J2.1 | length 1348.1
  Bottom Layer w10: J1.31 1605.62,888.58 1596,898.2 1596,939 1608,951 1680.46,951 1706.69,924.77 1897.35,924.77 1943.06,879.05 1943.06,142.06 1930,129 1853,129 1842.16,139.84 J2.1
CAM_3V3: C4.2 C9.2 C24.2 JP1.22 U1.3 U2.3 U3.3 | length 135.6
  Bottom Layer w18: U2.3 1577,1174.5 C9.2 ; U3.3 1738,1174.5 C24.2 ; U1.3 1899,1174.5 C4.2
CAM_MCLK: JP1.18 JP2.6 | length 1184.8
  Top Layer w10: v1(1226.38,297.38) 1226.38,328.38 1246.06,348.06 v1(1246.06,376.94)
  Bottom Layer w10: JP1.18 v1(1226.38,297.38) ; v1(1246.06,376.94) JP2.6
CAM_PWDN: JP2.7 R1.2 | length 430.4
  Top Layer w12: v1(1226.38,1055.62) 1226.38,994.62 1246,975 v1(1278,975)
  Bottom Layer w12: v1(1226.38,1055.62) JP2.7 ; v1(1278,975) R1.2
CAM_RST: JP1.17 JP2.8 R2.2 | length 1278.3
  Top Layer w10: v1(1206.69,318.69) 1206.69,341.43 1222,356.74 v1(1222,399) ; v1(1222,932) v1(1282,932)
  Bottom Layer w10: JP1.17 v1(1206.69,318.69) ; JP2.8 1206.69,1031.31 1222,1016 v1(1222,399) ; v1(1282,932) R2.2
CAM_SCL: JP1.20 JP2.9 R3.2 | length 1333.2
  Top Layer w10: v1(1204,890) v1(1282,890) ; v1(1265.75,258.75) v1(1265.75,321.75)
  Bottom Layer w10: JP2.9 1187.01,890 ; v1(1204,890) 1187.01,890 ; JP1.20 v1(1265.75,258.75) ; v1(1265.75,321.75) 1187.01,400.49 1187.01,890 ; v1(1282,890) R3.2
CAM_SDA: JP1.21 JP2.10 R7.2 | length 1404.3
  Top Layer w10: v1(1150,847) v1(1282,847)
  Bottom Layer w10: v1(1150,847) 1166.32,847 1167.32,848 ; JP2.10 1167.32,848 ; v1(1282,847) R7.2 ; JP1.21 1285.43,267.57 1167.32,385.68 1167.32,848
CSI_CLK_N: JP1.2 JP2.24 | length 1209
  SIG w4.79: v1(896.89,1279.16) 887.36,1269.63 887.36,1190.9 922,1156.26 922,232.1 v1(931.1,223)
  Bottom Layer w6: JP2.24 891.73,1296.16 896.89,1291 v1(896.89,1279.16) ; JP1.2 911.42,203.31 v1(931.1,223)
CSI_CLK_P: JP1.3 JP2.25 | length 1205.3
  SIG w4.79: v1(867.05,1279.16) 876.57,1269.63 876.57,1186.43 911.21,1151.79 911.21,215.68 v1(931.1,195.79)
  Bottom Layer w6: v1@866.89,1279.16 866.89,1291 872.05,1296.16 JP2.25 ; JP1.3 v1(931.1,195.79)
CSI_D0_N: JP1.5 JP2.21 | length 1209
  SIG w4.79: v1(955.94,1279.16) 946.42,1269.63 946.42,1206.84 981,1172.26 981,232.16 v1(990.16,223)
  Bottom Layer w6: JP2.21 950.79,1296.16 955.94,1291 v1(955.94,1279.16) ; JP1.5 970.47,203.31 v1(990.16,223)
CSI_D0_P: JP1.6 JP2.22 | length 1205.3
  SIG w4.79: v1(926.1,1279.16) 935.63,1269.63 935.63,1202.37 970.21,1167.79 970.21,215.74 v1(990.16,195.79)
  Bottom Layer w6: v1@925.94,1279.16 925.94,1291 931.1,1296.16 JP2.22 ; JP1.6 v1(990.16,195.79)
CSI_D1_N: JP1.8 JP2.18 | length 1209
  SIG w4.79: v1(1015,1279.16) 1005.47,1269.63 1005.47,1215.53 1041,1180 1041,231.21 v1(1049.21,223)
  Bottom Layer w6: JP2.18 1009.84,1296.16 1015,1291 v1(1015,1279.16) ; JP1.8 1029.53,203.31 v1(1049.21,223)
CSI_D1_P: JP1.9 JP2.19 | length 1205.3
  SIG w4.79: v1(985.16,1279.16) 994.68,1269.63 994.68,1211.06 999.37,1206.37 1030.21,1175.53 1030.21,214.79 v1(1049.21,195.79)
  Bottom Layer w6: v1@985,1279.16 985,1291 990.16,1296.16 JP2.19 ; JP1.9 v1(1049.21,195.79)
DOVDD_1V8: C1.2 C2.2 C3.2 JP2.5 R1.1 R2.1 R3.1 R7.1 R8.2 | length 1340.3
  Bottom Layer w12: R7.1 R3.1 R2.1 R1.1 1351,1094 1265.75,1179.25 JP2.5 1265.75,1397.49 1288.25,1420 1834.33,1420 1855,1399.33 C3.2 C2.2 C1.2 R8.2
DVDD_1V2: C5.2 C6.2 C7.2 C8.2 JP2.2 R9.2 | length 662.2
  Bottom Layer w12: JP2.2 1324.8,1178.2 1345,1158 1457,1158 1476,1177 1476,1335.55 1488.45,1348 C8.2 C7.2 C6.2 C5.2 R9.2
GND: C1.1 C2.1 C3.1 C4.1 C5.1 C6.1 C7.1 C8.1 C9.1 C10.1 C11.2 C12.2 C13.1 C14.1 C15.1 C16.1 C17.1 C18.1 C19.1 C20.1 C21.1 C22.1 C23.1 C24.1 C25.1 C26.1 C27.1 C28.1 C29.1 C30.1 J1.9 J1.10 J1.13 J1.16 J1.19 J1.22 J1.25 J1.28 J1.32 J1.33 J2.4 J2.7 J2.10 J2.13 J2.16 J2.19 J2.22 J2.23 J2.32 J2.33 JP1.1 JP1.4 JP1.7 JP1.10 JP1.13 JP1.16 JP1.19 JP2.1 JP2.11 JP2.14 JP2.17 JP2.20 JP2.23 JP2.26 JP3.0 JP3.7 JP3.8 M1.1 M2.1 M3.1 M4.1 R5.1 R6.1 R12.2 U1.1 U2.1 U3.1 U4.11 U4.18 U4.20 U4.25 U5.2 U6.1 U7.2 U8.7 | length 8682
  Top Layer w10: v1(1664.99,335.99) v1(1664.99,376.99)
  SIG w10: v1(858,1257) 858,1174 891.73,1140.27 v1(891.73,112.16)
  SIG w12: v1(911,1257) 911,1193 950.79,1153.21 v1(950.79,112.16) ; v1(970,1258) 970,1210 1009.84,1170.16 v1(1009.84,112.16) ; v1(1034,1258) 1034,1215 1068.9,1180.1 v1(1068.9,112.16)
  Bottom Layer w8: v1(266,718) R12.2 ; JP3.8 v1(560.78,361.43) ; v1(580.47,221) JP3.7 ; C14.1 v1(643,891.34) ; U4.11 688.51,734.82 v1(712.13,711.2) 735.75,734.82 U4.20 v1(802.64,734.82) ; C13.1 v1(673,891.34) ; U4.18 v1(751.5,797.84) ; JP2.26 852.36,1293.36 847,1288 847,1268 v1(858,1257) ; JP2.17 1029.53,1297.47 1034,1293 v1(1034,1258)
  Bottom Layer w10: v1(891.73,112.16) JP1.1 ; v1(950.79,112.16) JP1.4 ; v1(1009.84,112.16) JP1.7 ; v1(1068.9,112.16) JP1.10 ; v1(1088.58,1277.58) JP2.14 ; v1(1147.64,1277.58) JP2.11 ; v1(1426.43,187.57) J2.33 ; v1(1510,611) 1571,611 1588.74,628.74 J1.9 1660.63,628.74 1662.13,627.24 1681.59,627.24 1698.84,610 v1(1701,610) ; v1(1560,657) 1578.98,675.98 J1.13 1660.02,675.98 1674,662 v1(1696,662) ; v1(1582.32,144.43) J2.23 ; v1(1594.14,240.14) J2.22 v1(1594.14,353.86) ; v1(1596.85,746.85) J1.19 v1(1667.15,746.85) ; v1(1629.56,144.43) J2.19 ; J1.25 1665.06,817.71 1670.91,811.85 1670.91,798.09 v1(1671,798) 1692,798 1707.72,782.28 J1.22 ; v1(1649.49,418.51) J1.32 ; J1.33 1676.83,914.17 1682,909 v1(1682,887) ; J2.16 v1(1664.99,335.99) ; v1(1693,209) 1700.44,201.57 J2.13 v1(1700.44,144.43) ; v1(1735.86,253.14) J2.10 ; J1.10 v1(1782.45,640.55) ; J1.16 v1(1806.58,711.42) ; J1.28 1861.75,853.15 1874.9,840 v1(1877.06,840) ; J2.7 v1(1771.3,202.3) ; v1(1806.73,257.26) J2.4 ; J2.32 v1(1897.12,187.57)
  Bottom Layer w12: C28.1 C27.1 v1(199,870) ; v1(165,988) C29.1 v1(204,949) ; v1(177,1431) R5.1 ; v1(231,1339) U5.2 ; C19.1 v1(272,454) ; C26.1 v1(272,643) ; C30.1 v1(272,685) ; C15.1 245.5,1192.5 296.5,1192.5 v1(297,1193) ; U6.1 v1(296,588.5) ; C20.1 v1(338,583) ; C21.1 v1(370,583) ; v1(436,1431) R6.1 ; v1(448.05,192.78) JP3.0@482.05,192.78 ; v1(471,1339) U7.2 ; v1(471,1457) C18.1@471,1492 ; C17.1 v1(519,1189) ; v1(521.6,732.4) C12.2 ; C11.2 v1(637.06,605.4) ; JP3.0@737.95,192.78 v1(771.95,192.78) ; v1(1127.95,109.39) JP1.13 v1(1127.95,201.99) ; v1(1187.01,109.39) JP1.16 v1(1187.01,201.99) ; v1(1246.06,109.39) JP1.19 v1(1246.06,201.99) ; v1(1344.49,1286.14) JP2.1 ; v1(1496,1308) C8.1 C7.1 C6.1 C5.1 ; v1(1538.5,1210.5) U2.1 ; C9.1 v1(1641,1130) ; C23.1 C22.1 ; v1(1699.5,1215.5) U3.1 v1(1726,1255) C22.1 ; C10.1 C22.1 ; C24.1 v1(1802,1130) ; v1(1825,1255) U1.1 ; v1(1828,1308) C3.1 C2.1 C1.1 ; C4.1 v1(1963,1130)
  Bottom Layer w18: C25.1 1816,1389 1828,1377 v1(1828,1308)
  other v1: 887,284 946,285 1005,286 1064,287 272,356 321,356 887,370 946,371 1005,372 1064,373 84,405 133,405 272,405 321,405 726,406 563,428 84,454 133,454 321,454 887,456 946,457 1005,458 1064,459 686.06,507.4 735.06,507.4 521.6,536.4 570.6,536.4 887,542 946,543 1005,544 1064,545 84,550.5 133,550.5 1504,550 686.06,556.4 735.06,556.4 456,560 1607,584 521.6,585.4 2062.06,601 686.06,605.4 735.06,605.4 456,609 887,628 946,629 1005,630 1064,631 521.6,634.4 84,643 133,643 321,643 456,658 2062.06,660 521.6,683.4 84,685 133,685 321,685 456,707 887,714 946,715 1005,716 1064,717 2062.06,719 456,756 2062.06,778 521.6,781.4 802.64,783.82 887,800 946,801 1005,802 1064,803 456,805 199,821 248,821 802.64,832.82 2062.06,837 722,842.34 456,854 505,854 554,854 248,870 323,870 372,870 887,886 946,887 1005,888 1064,889 594,891.34 722,891.34 2062.06,896 456,903 505,903 554,903 2062.06,955 887,972 946,973 1005,974 1064,975 214,988 617,993 673,993 2062.06,1014 165,1037 214,1037 617,1042 673,1042 887,1058 946,1059 1005,1060 1064,1061 165,1086 214,1086 617,1091 673,1091 1271,1136 484,1140 617,1140 673,1140 887,1144 946,1145 1005,1146 1064,1147 617,1189 673,1189 617,1238 673,1238 617,1287 673,1287 617,1336 673,1336 230,1458
IMU_3V3: C11.1 C13.2 C14.2 L2.1 R4.1 U4.8 U4.13 | length 501
  Top Layer w12: v1(586.37,669.4) 586.37,783.71 595.13,792.46 v1(643,792.46)
  Bottom Layer w8: R4.1 564.06,788.4 570.06,794.4 608.06,794.4 613,799.34 L2.1 ; v1(586.37,669.4) C11.1 631.24,687.58 U4.8
  Bottom Layer w12: L2.1 C14.2 ; v1(643,792.46) C14.2 ; U4.13 672.76,822.76 C13.2 C14.2
IMU_CLK: JP3.2 U4.23 | length 558.7
  Bottom Layer w8: JP3.2 678.89,428.89 701.4,451.4 803.06,451.4 819.06,467.4 819.06,677.4 808.88,687.58 U4.23
IMU_CS: JP3.1 U4.22 | length 598.5
  Bottom Layer w8: JP3.1 698.58,418.58 712.4,432.4 825.06,432.4 840.06,447.4 840.06,686.4 823.13,703.33 U4.22
IMU_INT: R4.2 U4.12 | length 56.8
  Bottom Layer w8: R4.2 627.06,762.4 638.89,750.57 U4.12
IMU_MISO: JP3.4 U4.9 | length 519
  Bottom Layer w8: JP3.4 639.52,535.94 565.06,610.4 565.06,678 590.4,703.33 U4.9
IMU_MOSI: JP3.3 U4.24 | length 529.7
  Bottom Layer w8: JP3.3 659.21,448.21 678.4,467.4 787.06,467.4 799.06,479.4 799.06,666.4 793.63,671.83 U4.24
LED1_PWM: JP3.6 U5.4 | length 1239.7
  Top Layer w12: v1(268.4,1109.4) v1(268.4,1226)
  Bottom Layer w12: v1(268.4,1109.4) 268.4,961.6 290,940 383,940 408,915 408,500 445,463 573,463 600.15,435.85 JP3.6 ; v1(268.4,1226) U5.4
LED2_PWM: JP3.5 U7.4 | length 1221.5
  Bottom Layer w12: U7.4 v1(508.4,1226) 538,1226 553,1211 553,1165 498,1110 498,985 426,913 426,507.46 450.46,483 587,483 619.84,450.16 JP3.5
LIGHT_2V85: C15.2 C17.2 C27.2 C28.2 C29.2 C31.1 L1.2 L3.1 L4.1 R11.1 U5.6 U7.6 U8.2 | length 540.4
  Top Layer w8: v1(83,913) 272,913 298,887 v1(298,718)
  Bottom Layer w6: U8.2 275.57,772.43 R11.1
  Bottom Layer w8: v1(298,718) R11.1 C31.1
MIPI_TX0_N: J1.21 J2.11 | length 937.9
  SIG w4.79: v1(1666.97,770.47) 1682.29,785.79 1831.47,785.79 1862,755.26 1862,250.74 1829.22,217.97 1736.97,217.97 v1(1724.06,205.05)
  Bottom Layer w6: J1.21 v1(1666.97,770.47) ; J2.11 v1(1724.06,205.05)
MIPI_TX0_P: J1.20 J2.12 | length 942.6
  SIG w4.79: v1(1690.67,758.66) 1707.01,775 1827,775 1851.21,750.79 1851.21,255.21 1824.76,228.76 v1(1712.24,228.76)
  Bottom Layer w6: v1@1690.24,758.66 v1(1690.67,758.66) J1.20 ; v1@1712.24,228.33 v1(1712.24,228.76) J2.12
MIPI_TX1_N: J1.18 J2.14 | length 937.9
  SIG w4.79: v1(1688.62,256.95) 1673.79,271.79 1592.21,271.79 1576,288 1576,311.19 cw(c1582.24,311.19) 1582.24,317.42 1605.79,317.42 ccw(c1605.79,323.66) 1612.03,323.66 1612.03,331.98 ccw(c1605.79,331.98) 1605.79,338.21 1582.24,338.21 cw(c1582.24,344.45) 1576,344.45 1576,372 1576,390.61 1576,487.97 cw(c1582.24,487.97) 1582.24,494.21 1621.52,494.21 ccw(c1621.52,511.24) 1638.54,511.24 1638.54,519.55 ccw(c1621.52,519.55) 1621.52,536.58 1582.24,536.58 cw(c1582.24,542.82) 1576,542.82 1576,550.61 1576,616.74 1594.26,635 1709.26,635 1730.79,656.53 1730.79,723.12 v1(1718.87,735.04)
  Bottom Layer w6: v1(1688.62,256.95) J2.14 ; v1(1718.87,735.04) J1.18
MIPI_TX1_P: J1.17 J2.15 | length 938.8
  SIG w4.79: v1(1676.81,233.26) 1649.07,261 1587.74,261 1565.21,283.53 1565.21,390.61 1565.21,487.97 cw(c1582.24,487.97) 1582.24,505 1621.52,505 ccw(c1621.52,511.24) 1627.75,511.24 1627.75,519.55 ccw(c1621.52,519.55) 1621.52,525.79 1582.24,525.79 cw(c1582.24,542.82) 1565.21,542.82 1565.21,550.61 1565.21,621.21 1589.79,645.79 1704.79,645.79 1720,661 1720,698.4 v1(1695.17,723.23)
  Bottom Layer w6: J1.17 v1(1695.17,723.23) v1@1695.59,723.23 ; J2.15 v1(1676.81,233.26) v1@1676.81,233.68
MIPI_TX2_N: J1.15 J2.17 | length 940
  SIG w4.79: v1@1653.03,205.21 v1(1653.19,205.05) 1552.69,205.05 1530.37,227.37 1527.21,230.53 1527.21,247.16 1527.21,249.56 ccw(c1520.97,249.56) 1520.97,255.79 1509.84,255.79 cw(c1509.84,262.03) 1503.6,262.03 1503.6,270.35 cw(c1509.84,270.35) 1509.84,276.58 1520.97,276.58 ccw(c1520.97,282.82) 1527.21,282.82 1527.21,297.6 1527.21,334.23 1527.21,363.08 ccw(c1520.97,363.08) 1520.97,369.31 1517.7,369.31 cw(c1517.7,386.34) 1500.67,386.34 1500.67,394.66 cw(c1517.7,394.66) 1517.7,411.68 1521.01,411.68 ccw(c1521.01,417.92) 1527.24,417.92 1527.24,426.24 ccw(c1521.01,426.24) 1521.01,432.47 1492.82,432.47 cw(c1492.82,449.5) 1475.79,449.5 1475.79,457.82 cw(c1492.82,457.82) 1492.82,474.84 1520.97,474.84 ccw(c1520.97,481.08) 1527.21,481.08 1527.21,520.45 1527.21,664.47 1530.37,667.63 1550.74,688 1655.37,688 v1(1666.97,699.6)
  Bottom Layer w6: J1.15 v1(1666.97,699.6) ; J2.17 v1(1653.19,205.05)
MIPI_TX2_P: J1.14 J2.18 | length 940.7
  SIG w4.79: v1(1641.38,228.76) 1629.62,217 1556,217 1538,235 1538,334.23 1538,363.08 ccw(c1520.97,363.08) 1520.97,380.1 1517.7,380.1 cw(c1517.7,386.34) 1511.46,386.34 1511.46,394.66 cw(c1517.7,394.66) 1517.7,400.89 1521.01,400.89 ccw(c1521.01,417.92) 1538.03,417.92 1538.03,426.24 ccw(c1521.01,426.24) 1521.01,443.26 1492.82,443.26 cw(c1492.82,449.5) 1486.58,449.5 1486.58,457.82 cw(c1492.82,457.82) 1492.82,464.05 1520.97,464.05 ccw(c1520.97,481.08) 1538,481.08 1538,520.45 1538,660 1555.21,677.21 1680.09,677.21 v1(1690.67,687.79)
  Bottom Layer w6: v1@1641.38,228.33 v1(1641.38,228.76) J2.18 ; v1@1690.24,687.79 v1(1690.67,687.79) J1.14
NetC12_1: C12.1 U4.10 | length 57.4
  Bottom Layer w8: C12.1 628.06,732.4 641.39,719.07 U4.10
NetC16_2: C16.2 D1.1 LED1.2 U5.5 | length 324.5
  Top Layer w12: v1(121,1489) 121,1320 139,1302 v1(231,1302)
  Bottom Layer w12: U5.5 v1(231,1302)
  other v1: 103,1516 138,1516
NetC18_2: C18.2 D2.1 LED3.2 U7.5 | length 495.1
  Top Layer w12: v1(361,1489) 328.37,1489 318.82,1479.45 318.82,1466.03 311.79,1459 279,1459 268,1448 268,1318.64 284.64,1302 v1(471,1302)
  Bottom Layer w12: U7.5 v1(471,1302)
  other v1: 343,1516 378,1516
NetC31_2: C31.2 R11.2 R12.1 U8.1 | length 104.4
  Bottom Layer w8: U8.1 329.85,790.15 C31.2
NetD1_2: D1.2 L3.2 U5.1
NetD2_2: D2.2 L4.2 U7.1
NetL1_1: L1.1 U8.6
NetLED1_1: LED1.1 LED2.2 | length 1992.7
  Top Layer w28: LED1.1 240.65,1625.02 256.18,1609.49 256.18,1591.4 272.58,1575 432,1575 525,1482 861,1482 950,1393 1246,1393 1335,1482 1667,1482 1746,1561 1966,1561 1979,1574 LED2.2
NetLED2_1: LED2.1 R13.2 | length 1434.4
  Top Layer w28: v1(717,1385) 861.83,1385 921.83,1325 1274.17,1325 1363.17,1414 1941,1414 1979,1452 LED2.1
  Bottom Layer w20: R13.2 v1(717,1385)
NetLED3_1: LED3.1 LED4.2 | length 1632
  Top Layer w28: LED3.1 438.98,1625.02 547.65,1516.35 875.65,1516.35 965,1427 1231,1427 1320.35,1516.35 1648.35,1516.35 1757.02,1625.02 LED4.2
NetLED4_1: LED4.1 R14.2 | length 1248.5
  Top Layer w28: v1(717,1431) 863.92,1431 935.92,1359 1260.08,1359 1349.08,1448 1681.08,1448 1736.06,1502.98 LED4.1
  Bottom Layer w20: R14.2 v1(717,1431)
NetR5_2: R5.2 R13.1 U5.3 | length 425.2
  Top Layer w25: v1(312,1431) 359,1431 405,1385 v1(573,1385)
  Bottom Layer w20: U5.3 268.4,1430.6 R5.2 v1(312,1431) ; v1(573,1385) R13.1
NetR6_2: R6.2 R14.1 U7.3 | length 154.7
  Bottom Layer w20: U7.3 508.4,1412.4 R6.2 R14.1
NetR8_1: R8.1 U1.2
NetR9_1: R9.1 U2.2 | length 85.5
  Bottom Layer w18: U2.2 1641,1255 1653,1267 R9.1
NetR10_1: R10.1 U3.2
pads on no net: JP1.0 JP1.11 JP1.12 JP1.14 JP1.15 JP2.0 JP2.3 JP2.12 JP2.13 JP2.15 JP2.16 U4.1 U4.2 U4.3 U4.4 U4.5 U4.6 U4.7 U4.14 U4.15 U4.16 U4.17 U4.19 U4.21 U8.3

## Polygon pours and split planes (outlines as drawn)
GND on Bottom Layer "GND_L04_P033" (solid, remove dead copper, pour order 33): -3.02,0 -3.02,80 -2.13,82.13 34.98,119.25 34.98,1372.75 -2.13,1409.87 -3.02,1412 -3.02,1492 cw(c120.71,1492) 33.22,1579.49 130.51,1676.78 cw(c218,1589.29) 218,1713.02 365,1713.02 cw(c365,1589.29) 452.49,1676.78 536.78,1592.49 ccw(c620,1675.71) 620,1558.02 689.15,1558.02 ccw(c689.15,1639.14) 746.51,1581.78 ccw(c663.29,1665) 780.98,1665 780.98,1703 cw(c904.71,1703) 817.22,1790.49 885.94,1859.2 cw(c973.42,1771.71) 973.42,1895.44 1223.42,1895.44 cw(c1223.42,1771.71) 1310.91,1859.2 1379.63,1790.49 cw(c1292.14,1703) 1415.86,1703 1415.86,1665 ccw(c1533.56,1665) 1450.34,1581.78 ccw(c1507.7,1639.14) 1507.7,1558.02 1576.85,1558.02 ccw(c1576.85,1675.71) 1660.07,1592.49 1744.36,1676.78 cw(c1831.85,1589.29) 1831.85,1713.02 1978.85,1713.02 cw(c1978.85,1589.29) 2066.34,1676.78 2163.63,1579.49 cw(c2076.14,1492) 2199.86,1492 2199.86,1422.83 2199.87,0 2196.85,-3.01
LIGHT_2V85 on Bottom Layer "LIGHT_2V85_L04_P015" (solid, remove dead copper, pour order 15): 443,1285 443,1142 424.95,1123.95 66,1123.95 66,1285 176,1285 203,1285 203,1210 203,1170 213,1160 304,1160 314,1170 314,1276 323,1285
LIGHT_2V85 on Bottom Layer "LIGHT_2V85_L04_P030" (solid, remove dead copper, pour order 30): 66,804 66,1140 135,1140 135,935 122,922 122,804
NetL1_1 on Bottom Layer "NETL1_1_L04_P029" (solid, remove dead copper, pour order 29): 204,778 66,778 66,738 144,738 173,767 204,767
5V on Bottom Layer "5V_L04_P028" (solid, remove dead copper, pour order 28): 547,307 230,307 207,330 207,760 175,760 156,741 156,301 189,268 547,268
AVDD_2V8 on Bottom Layer "AVDD_2V8_L04_P024" (solid, remove dead copper, pour order 24): 1743,1387 1743,1344 1737,1338 1719,1338 1715,1342 1715,1387
CAM_3V3 on Bottom Layer "CAM_3V3_L04_P023" (solid, remove dead copper, pour order 23): 1299,130 1299,778 1332,811 1378,811 1392,825 1392,1090 1429,1127 1480,1127 1527,1174 1917,1174 1917,1150 1556,1150 1502,1096 1449,1096 1433,1080 1433,808 1400,775 1361,775 1340,754 1340,336 1322,318 1322,130
NetR8_1 on Bottom Layer "NETR8_1_L04_P022" (solid, remove dead copper, pour order 22): 1940,1318 1940,1301 1917,1278 1917,1232 1954,1232 1954,1288 1962,1296 1962,1318
NetR10_1 on Bottom Layer "NETR10_1_L04_P021" (solid, remove dead copper, pour order 21): 1780,1318 1780,1302 1756,1278 1756,1232 1793,1232 1793,1276 1802,1285 1802,1318
NetD2_2 on Bottom Layer "NETD2_2_L04_P014" (solid, remove dead copper, pour order 14): 443,1394 323,1394 314,1385 314,1306 414,1306 443,1335
NetD1_2 on Bottom Layer "NETD1_2_L04_P013" (solid, remove dead copper, pour order 13): 203,1394 83,1394 74,1385 74,1306 174,1306 203,1335
NetC18_2 on Bottom Layer "NETC18_2_L04_P011" (solid, remove dead copper, pour order 11): 326,1475 326,1534 441,1534 441,1475 415,1475
NetC16_2 on Bottom Layer "NETC16_2_L04_P009" (solid, remove dead copper, pour order 9): 86,1475 86,1534 201,1534 201,1475 175,1475
GND on Top Layer "GND_L01_P031" (solid, remove dead copper, pour order 31): -3.02,0 -3.02,80 -2.13,82.13 34.98,119.25 34.98,1372.75 -2.13,1409.87 -3.02,1412 -3.02,1492 cw(c120.71,1492) 33.22,1579.49 130.51,1676.78 cw(c218,1589.29) 218,1713.02 365,1713.02 cw(c365,1589.29) 452.49,1676.78 536.78,1592.49 ccw(c620,1675.71) 620,1558.02 689.15,1558.02 ccw(c689.15,1639.14) 746.51,1581.78 ccw(c663.29,1665) 780.98,1665 780.98,1703 cw(c904.71,1703) 817.22,1790.49 885.94,1859.2 cw(c973.42,1771.71) 973.42,1895.44 1223.42,1895.44 cw(c1223.42,1771.71) 1310.91,1859.2 1379.63,1790.49 cw(c1292.14,1703) 1415.86,1703 1415.86,1665 ccw(c1533.56,1665) 1450.34,1581.78 ccw(c1507.7,1639.14) 1507.7,1558.02 1576.85,1558.02 ccw(c1576.85,1675.71) 1660.07,1592.49 1744.36,1676.78 cw(c1831.85,1589.29) 1831.85,1713.02 1978.85,1713.02 cw(c1978.85,1589.29) 2066.34,1676.78 2163.63,1579.49 cw(c2076.14,1492) 2199.86,1492 2199.86,1422.83 2199.87,0 2196.85,-3.01
NetC18_2 on Top Layer "NETC18_2_L01_P012" (solid, remove dead copper, pour order 12): 326,1534 441,1534 441,1475 326,1475
NetC16_2 on Top Layer "NETC16_2_L01_P010" (solid, remove dead copper, pour order 10): 86,1534 201,1534 201,1475 86,1475
GND on SIG "GND_L03_P032" (solid, remove dead copper, pour order 32): -3.02,0 -3.02,80 -2.13,82.13 34.98,119.25 34.98,1372.75 -2.13,1409.87 -3.02,1412 -3.02,1492 cw(c120.71,1492) 33.22,1579.49 130.51,1676.78 cw(c218,1589.29) 218,1713.02 365,1713.02 cw(c365,1589.29) 452.49,1676.78 536.78,1592.49 ccw(c620,1675.71) 620,1558.02 689.15,1558.02 ccw(c689.15,1639.14) 746.51,1581.78 ccw(c663.29,1665) 780.98,1665 780.98,1703 cw(c904.71,1703) 817.22,1790.49 885.94,1859.2 cw(c973.42,1771.71) 973.42,1895.44 1223.42,1895.44 cw(c1223.42,1771.71) 1310.91,1859.2 1379.63,1790.49 cw(c1292.14,1703) 1415.86,1703 1415.86,1665 ccw(c1533.56,1665) 1450.34,1581.78 ccw(c1507.7,1639.14) 1507.7,1558.02 1576.85,1558.02 ccw(c1576.85,1675.71) 1660.07,1592.49 1744.36,1676.78 cw(c1831.85,1589.29) 1831.85,1713.02 1978.85,1713.02 cw(c1978.85,1589.29) 2066.34,1676.78 2163.63,1579.49 cw(c2076.14,1492) 2199.86,1492 2199.86,1422.83 2199.87,0 2196.85,-3.01
GND on GND (split plane): 408 vertices, not listed, extent 17.08,17.11 2179.77,1875.34

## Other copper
Top Layer:
  text "1-TOP 2-GND 3-SIG 4-BOT" at 413,-157 h60

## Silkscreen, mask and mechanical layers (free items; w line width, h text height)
Top Overlay:
  lines w6: 460.24,427.24 460.24,994.17 1405.12,994.17 1405.12,427.24 460.24,427.24 ; 1594.09,427.24 1594.09,994.17 1735.83,994.17 1735.83,427.24 1594.09,427.24
  lines w12: 350,317 350,1104.4 1846.06,1104.4 1846.06,317 350,317
  text "1 - 31" at 1850,556 h60 r90
  text "1 - 31" at 1522,68 h60
Mechanical 1:
  circle w10: c1098.43,1661.4 r196.06
  lines w6: 0,1422.83 0,1492 ; 0,1492 cw(c120.71,1492) 35.36,1577.36 132.64,1674.64 cw(c218,1589.29) 218,1710 365,1710 cw(c365,1589.29) 450.36,1674.64 534.64,1590.36 ccw(c620,1675.71) 620,1555 689.15,1555 ccw(c689.15,1639.14) 748.64,1579.64 ccw(c663.29,1665) 784,1665 784,1703 cw(c904.71,1703) 819.36,1788.36 888.07,1857.07 cw(c973.42,1771.71) 973.42,1892.42 1098.42,1892.42 1223.42,1892.42 cw(c1223.42,1771.71) 1308.78,1857.07 1377.49,1788.36 cw(c1292.14,1703) 1412.85,1703 1412.85,1665 ccw(c1533.56,1665) 1448.21,1579.64 ccw(c1507.7,1639.14) 1507.7,1555 1576.85,1555 ccw(c1576.85,1675.71) 1662.21,1590.36 1746.49,1674.64 cw(c1831.85,1589.29) 1831.85,1710 1978.85,1710 cw(c1978.85,1589.29) 2064.21,1674.64 2161.49,1577.36 cw(c2076.14,1492) 2196.85,1492 2196.85,1422.83 2196.85,0 0,0 0,80 38,118 38,1374 0,1412 0,1492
